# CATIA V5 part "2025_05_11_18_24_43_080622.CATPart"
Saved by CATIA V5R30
Part number: 2025_05_11_18_24_43_080622
Definition: 2025_05_11_18_24_43_0806
Nomenclature: 2025_05_11_18_24_43_0806
Source: Unknown
Description: PART--DESC
Bounding box of the stored display mesh (mm): x -12.75 to 12.75, y -12.75 to 12.75, z 0 to 53
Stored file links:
  E:\Bakalarka\Model\Forma_v7\2025_05_11_18_24_43_080622.CATPart
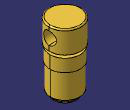
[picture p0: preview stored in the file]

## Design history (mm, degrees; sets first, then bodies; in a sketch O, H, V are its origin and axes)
Body1 "MANIFOLD_SOLID_BREP #164" (main body)
  Solid1: solid without history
